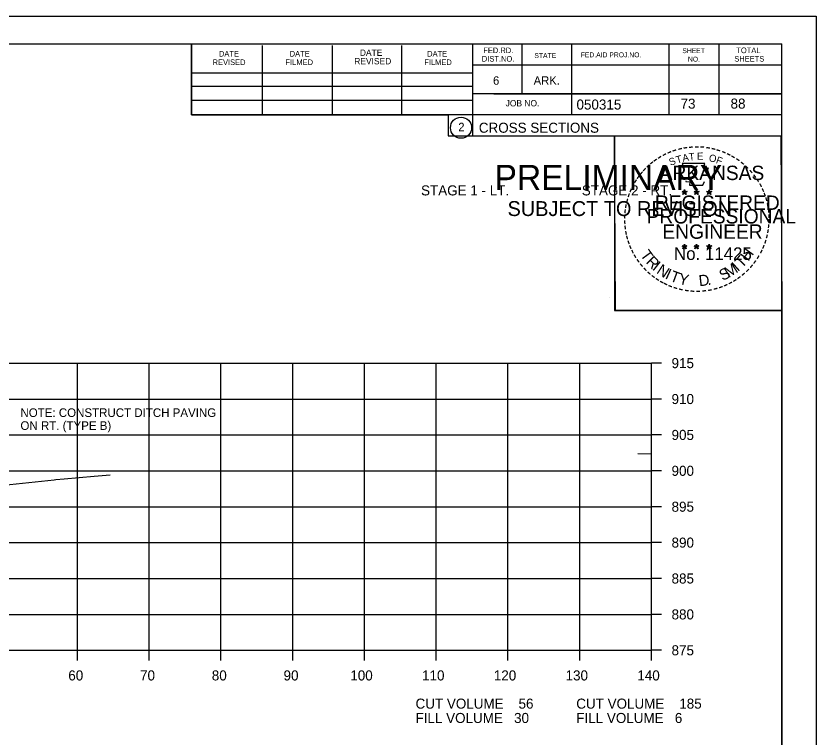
# Model space of a CAD drawing. Extents: x 1486524 to 1499135, y 326561 to 337924.
# Drawn here: x 1489034.3 to 1489145.8, y 333105.4 to 333206 of the extents above; entities that cross this region are included whole.
import ezdxf

# ---------------------------------------------------------------- set-up
doc = ezdxf.new("R2010")
doc.units = 0
for name, color, linetype in [('Default', 7, 'Continuous'), ('E_Const Align', 7, 'Continuous'), ('E_Const Align Station', 7, 'Continuous'), ('E_Ownership Information', 7, 'Continuous'), ('E_Property Line', 7, 'Continuous'), ('E_Quarter Calls', 7, 'Continuous'), ('E_Section Line', 7, 'Continuous'), ('E_Station Offset', 7, 'Continuous'), ('E_Tract Number', 7, 'Continuous'), ('S_SIXTEEN_SECTION', 7, 'Continuous')]:
    doc.layers.add(name, color=color, linetype=linetype)

msp = doc.modelspace()

# ---------------------------------------------------------------- linework, layer by layer
at = {"layer": 'E_Const Align'}
for p, q in [((1489122.89, 333117.63), (1489122.89, 333157.63)), ((1489124.29, 333157.63), (1489122.89, 333157.63)), ((1489124.29, 333152.63), (1489122.89, 333152.63)), ((1489124.29, 333147.63), (1489122.89, 333147.63)), ((1489124.29, 333142.63), (1489122.89, 333142.63)), ((1489124.29, 333137.63), (1489122.89, 333137.63)), ((1489124.29, 333132.63), (1489122.89, 333132.63)), ((1489124.29, 333127.63), (1489122.89, 333127.63)), ((1489124.29, 333122.63), (1489122.89, 333122.63)), ((1488842.89, 333117.63), (1489122.89, 333117.63)), ((1489042.89, 333116.23), (1489042.89, 333117.63)), ((1489052.89, 333116.23), (1489052.89, 333117.63)), ((1489062.89, 333116.23), (1489062.89, 333117.63)), ((1489072.89, 333116.23), (1489072.89, 333117.63)), ((1489082.89, 333116.23), (1489082.89, 333117.63)), ((1489092.89, 333116.23), (1489092.89, 333117.63)), ((1489102.89, 333116.23), (1489102.89, 333117.63)), ((1489112.89, 333116.23), (1489112.89, 333117.63)), ((1489122.89, 333116.23), (1489122.89, 333117.63)), ((1489124.29, 333117.63), (1489122.89, 333117.63))]:
    msp.add_line(p, q, dxfattribs=at)
at = {"layer": 'E_Ownership Information'}
for p, q in [((1488842.89, 333157.63), (1489122.89, 333157.63)), ((1488842.89, 333157.63), (1489122.89, 333157.63)), ((1489042.89, 333117.63), (1489042.89, 333157.63)), ((1489042.89, 333117.63), (1489042.89, 333157.63)), ((1489052.89, 333117.63), (1489052.89, 333157.63)), ((1489052.89, 333117.63), (1489052.89, 333157.63)), ((1489062.89, 333117.63), (1489062.89, 333157.63)), ((1489062.89, 333117.63), (1489062.89, 333157.63)), ((1489072.89, 333117.63), (1489072.89, 333157.63)), ((1489072.89, 333117.63), (1489072.89, 333157.63)), ((1489082.89, 333117.63), (1489082.89, 333157.63)), ((1489082.89, 333117.63), (1489082.89, 333157.63)), ((1489092.89, 333117.63), (1489092.89, 333157.63)), ((1489092.89, 333117.63), (1489092.89, 333157.63)), ((1489102.89, 333117.63), (1489102.89, 333157.63)), ((1489102.89, 333117.63), (1489102.89, 333157.63)), ((1489112.89, 333117.63), (1489112.89, 333157.63)), ((1489112.89, 333117.63), (1489112.89, 333157.63)), ((1489122.89, 333117.63), (1489122.89, 333157.63)), ((1489122.89, 333117.63), (1489122.89, 333157.63)), ((1488842.89, 333152.63), (1489122.89, 333152.63)), ((1488842.89, 333152.63), (1489122.89, 333152.63)), ((1488842.89, 333147.63), (1489122.89, 333147.63)), ((1488842.89, 333147.63), (1489122.89, 333147.63)), ((1488842.89, 333142.63), (1489122.89, 333142.63)), ((1488842.89, 333142.63), (1489122.89, 333142.63)), ((1488842.89, 333137.63), (1489122.89, 333137.63)), ((1488842.89, 333137.63), (1489122.89, 333137.63)), ((1488842.89, 333132.63), (1489122.89, 333132.63)), ((1488842.89, 333132.63), (1489122.89, 333132.63)), ((1488842.89, 333127.63), (1489122.89, 333127.63)), ((1488842.89, 333127.63), (1489122.89, 333127.63)), ((1488842.89, 333122.63), (1489122.89, 333122.63)), ((1488842.89, 333122.63), (1489122.89, 333122.63)), ((1488842.89, 333117.63), (1489122.89, 333117.63)), ((1488842.89, 333117.63), (1489122.89, 333117.63))]:
    msp.add_line(p, q, dxfattribs=at)
at = {"layer": 'E_Property Line'}
for p, q in [((1488824.89, 333202.09), (1489141.07, 333202.09)), ((1489058.81, 333192.21), (1489058.81, 333202.09)), ((1489068.67, 333192.21), (1489068.67, 333201.89)), ((1489078.43, 333192.21), (1489078.43, 333201.89)), ((1489088.11, 333192.21), (1489088.11, 333201.89)), ((1489097.97, 333202.09), (1489097.97, 333189.29)), ((1489104.81, 333202.09), (1489104.81, 333195.15)), ((1489111.75, 333202.09), (1489111.75, 333192.21)), ((1489125.33, 333202.09), (1489125.33, 333192.21)), ((1489132.27, 333202.09), (1489132.27, 333192.21)), ((1489141.07, 332996.63), (1489141.07, 333202.09)), ((1489141.07, 333199.15), (1489097.97, 333199.15)), ((1489141.07, 333199.17), (1489141.07, 333199.17)), ((1489058.81, 333198.07), (1489097.97, 333198.07)), ((1489058.81, 333196.21), (1489097.97, 333196.21)), ((1489141.07, 333195.15), (1489097.97, 333195.15)), ((1489100.93, 333195.15), (1489141.07, 333195.15)), ((1489058.81, 333192.21), (1489058.81, 333194.27)), ((1489058.81, 333194.27), (1489097.97, 333194.27)), ((1489141.07, 333192.21), (1489058.81, 333192.21)), ((1489097.97, 333189.29), (1489141.07, 333189.29))]:
    msp.add_line(p, q, dxfattribs=at)
msp.add_circle((1489096.35, 333190.42), 1.47, dxfattribs=at)
at = {"layer": 'E_Quarter Calls'}
for p, q in [((1488812.48, 333205.98), (1489145.82, 333205.98)), ((1489117.1, 333166.83), (1489117.1, 333166.83))]:
    msp.add_line(p, q, dxfattribs=at)
for points in [[(1488812.48, 333205.98), (1489145.82, 333205.98), (1489145.82, 332992.64), (1488812.48, 332992.64)], [(1489058.81, 333202.09), (1489058.81, 333192.21), (1489094.54, 333192.21), (1489094.54, 333189.29), (1489117.74, 333189.29), (1489117.74, 333164.95), (1489141.07, 333164.95), (1489141.07, 332996.63), (1488824.89, 332996.63), (1488824.89, 333202.09)], [(1489117.74, 333189.29), (1489140.94, 333189.29), (1489141.07, 333164.95), (1489117.86, 333164.95)]]:
    msp.add_lwpolyline(points, close=True, dxfattribs=at)
at = {"layer": 'E_Tract Number'}
for points in [[(1489121.01, 333145.02), (1489122.89, 333145)], [(1489029.01, 333140.26), (1489039.63, 333141.38), (1489039.88, 333141.4), (1489041.05, 333141.5), (1489045.21, 333141.88), (1489047.46, 333142.07)]]:
    msp.add_lwpolyline(points, dxfattribs=at)
at = {"layer": 'S_SIXTEEN_SECTION'}
for p, q in [((1489127.15, 333181.54), (1489127.5, 333181.43)), ((1489127.15, 333181.54), (1489127.4, 333181.5)), ((1489127.15, 333181.54), (1489127.39, 333181.42)), ((1489127.28, 333181.13), (1489127.5, 333181.43)), ((1489127.28, 333181.13), (1489127.41, 333181.38)), ((1489127.28, 333181.13), (1489127.5, 333181.35)), ((1489127.5, 333181.8), (1489127.46, 333181.54)), ((1489127.5, 333181.43), (1489127.5, 333181.8)), ((1489127.5, 333181.8), (1489127.55, 333181.55)), ((1489127.85, 333181.54), (1489127.5, 333181.43)), ((1489127.71, 333181.13), (1489127.5, 333181.43)), ((1489127.71, 333181.13), (1489127.5, 333181.35)), ((1489127.85, 333181.54), (1489127.56, 333181.49)), ((1489127.71, 333181.13), (1489127.58, 333181.43)), ((1489127.85, 333181.54), (1489127.64, 333181.44)), ((1489128.82, 333181.54), (1489129.17, 333181.43)), ((1489128.82, 333181.54), (1489129.07, 333181.5)), ((1489128.82, 333181.54), (1489129.06, 333181.42)), ((1489128.95, 333181.13), (1489129.17, 333181.43)), ((1489128.95, 333181.13), (1489129.08, 333181.38)), ((1489128.95, 333181.13), (1489129.17, 333181.35)), ((1489129.17, 333181.8), (1489129.13, 333181.54)), ((1489129.17, 333181.43), (1489129.17, 333181.8)), ((1489129.17, 333181.8), (1489129.22, 333181.55)), ((1489129.52, 333181.54), (1489129.17, 333181.43)), ((1489129.38, 333181.13), (1489129.17, 333181.43)), ((1489129.38, 333181.13), (1489129.17, 333181.35)), ((1489129.52, 333181.54), (1489129.23, 333181.49)), ((1489129.38, 333181.13), (1489129.25, 333181.43)), ((1489129.52, 333181.54), (1489129.31, 333181.44)), ((1489130.58, 333181.53), (1489130.93, 333181.42)), ((1489130.58, 333181.53), (1489130.84, 333181.49)), ((1489130.58, 333181.53), (1489130.82, 333181.41)), ((1489130.72, 333181.12), (1489130.93, 333181.42)), ((1489130.72, 333181.12), (1489130.84, 333181.37)), ((1489130.72, 333181.12), (1489130.93, 333181.34)), ((1489130.93, 333181.78), (1489130.89, 333181.53)), ((1489130.93, 333181.42), (1489130.93, 333181.78)), ((1489130.93, 333181.78), (1489130.98, 333181.53)), ((1489131.28, 333181.53), (1489130.93, 333181.42)), ((1489131.15, 333181.12), (1489130.93, 333181.42)), ((1489131.15, 333181.12), (1489130.93, 333181.34)), ((1489131.28, 333181.53), (1489130.99, 333181.48)), ((1489131.15, 333181.12), (1489131.01, 333181.41)), ((1489131.28, 333181.53), (1489131.08, 333181.43)), ((1489127.15, 333173.97), (1489127.5, 333173.86)), ((1489127.15, 333173.97), (1489127.4, 333173.92)), ((1489127.15, 333173.97), (1489127.38, 333173.85)), ((1489127.28, 333173.56), (1489127.5, 333173.86)), ((1489127.28, 333173.56), (1489127.41, 333173.81)), ((1489127.28, 333173.56), (1489127.49, 333173.78)), ((1489127.5, 333174.22), (1489127.45, 333173.97)), ((1489127.71, 333173.56), (1489127.49, 333173.78)), ((1489127.5, 333173.86), (1489127.5, 333174.22)), ((1489127.5, 333174.22), (1489127.54, 333173.97)), ((1489127.84, 333173.97), (1489127.5, 333173.86)), ((1489127.71, 333173.56), (1489127.5, 333173.86)), ((1489127.84, 333173.97), (1489127.56, 333173.92)), ((1489127.71, 333173.56), (1489127.57, 333173.85)), ((1489127.84, 333173.97), (1489127.64, 333173.87)), ((1489128.82, 333173.97), (1489129.16, 333173.86)), ((1489128.82, 333173.97), (1489129.07, 333173.92)), ((1489128.82, 333173.97), (1489129.05, 333173.85)), ((1489128.95, 333173.56), (1489129.16, 333173.86)), ((1489128.95, 333173.56), (1489129.07, 333173.81)), ((1489128.95, 333173.56), (1489129.16, 333173.78)), ((1489129.16, 333174.22), (1489129.12, 333173.97)), ((1489129.16, 333173.86), (1489129.16, 333174.22)), ((1489129.16, 333174.22), (1489129.21, 333173.97)), ((1489129.51, 333173.97), (1489129.16, 333173.86)), ((1489129.38, 333173.56), (1489129.16, 333173.86)), ((1489129.38, 333173.56), (1489129.16, 333173.78)), ((1489129.51, 333173.97), (1489129.23, 333173.92)), ((1489129.38, 333173.56), (1489129.24, 333173.85)), ((1489129.51, 333173.97), (1489129.31, 333173.87)), ((1489130.58, 333173.96), (1489130.93, 333173.85)), ((1489130.58, 333173.96), (1489130.84, 333173.91)), ((1489130.58, 333173.96), (1489130.82, 333173.84)), ((1489130.72, 333173.55), (1489130.93, 333173.85)), ((1489130.72, 333173.55), (1489130.84, 333173.8)), ((1489130.72, 333173.55), (1489130.93, 333173.77)), ((1489130.93, 333174.21), (1489130.89, 333173.96)), ((1489130.93, 333173.85), (1489130.93, 333174.21)), ((1489130.93, 333174.21), (1489130.98, 333173.96)), ((1489131.28, 333173.96), (1489130.93, 333173.85)), ((1489131.14, 333173.55), (1489130.93, 333173.85)), ((1489131.14, 333173.55), (1489130.93, 333173.77)), ((1489131.28, 333173.96), (1489130.99, 333173.91)), ((1489131.14, 333173.55), (1489131.01, 333173.84)), ((1489131.28, 333173.96), (1489131.07, 333173.86))]:
    msp.add_line(p, q, dxfattribs=at)
for points in [[(1489127.19, 333185.42), (1489127.46, 333184.59)], [(1489130.7, 333184.5), (1489130.84, 333184.78), (1489130.16, 333184.76), (1489130.31, 333185.42), (1489127.19, 333185.42)], [(1489127.68, 333183), (1489127.68, 333182.91), (1489128.25, 333182.89), (1489128.19, 333182.42), (1489130.06, 333182.42), (1489130.26, 333182.95)], [(1489127.5, 333181.8), (1489127.71, 333181.13), (1489127.15, 333181.54), (1489127.85, 333181.54), (1489127.28, 333181.13), (1489127.5, 333181.8)], [(1489129.17, 333181.8), (1489129.38, 333181.13), (1489128.82, 333181.54), (1489129.52, 333181.54), (1489128.95, 333181.13), (1489129.17, 333181.8)], [(1489130.93, 333181.78), (1489131.15, 333181.12), (1489130.58, 333181.53), (1489131.28, 333181.53), (1489130.72, 333181.12), (1489130.93, 333181.78)], [(1489127.5, 333174.22), (1489127.71, 333173.56), (1489127.15, 333173.97), (1489127.84, 333173.97), (1489127.28, 333173.56), (1489127.5, 333174.22)], [(1489129.16, 333174.22), (1489129.38, 333173.56), (1489128.82, 333173.97), (1489129.51, 333173.97), (1489128.95, 333173.56), (1489129.16, 333174.22)], [(1489130.93, 333174.21), (1489131.14, 333173.55), (1489130.58, 333173.96), (1489131.28, 333173.96), (1489130.72, 333173.55), (1489130.93, 333174.21)]]:
    msp.add_lwpolyline(points, dxfattribs=at)
for centre, radius in [((1489127.5, 333181.43), 0.172), ((1489127.5, 333181.43), 0.145), ((1489127.5, 333181.43), 0.116), ((1489127.5, 333181.43), 0.0991), ((1489127.5, 333181.43), 0.0747), ((1489127.5, 333181.43), 0.0495), ((1489127.5, 333181.43), 0.0296), ((1489129.17, 333181.43), 0.172), ((1489129.17, 333181.43), 0.145), ((1489129.17, 333181.43), 0.116), ((1489129.17, 333181.43), 0.0991), ((1489129.17, 333181.43), 0.0747), ((1489129.17, 333181.43), 0.0495), ((1489129.17, 333181.43), 0.0296), ((1489130.93, 333181.42), 0.172), ((1489130.93, 333181.42), 0.145), ((1489130.93, 333181.42), 0.116), ((1489130.93, 333181.42), 0.0991), ((1489130.93, 333181.42), 0.0747), ((1489130.93, 333181.42), 0.0495), ((1489130.93, 333181.42), 0.0296), ((1489127.49, 333173.86), 0.172), ((1489127.49, 333173.86), 0.145), ((1489127.49, 333173.86), 0.116), ((1489127.49, 333173.86), 0.0991), ((1489127.49, 333173.86), 0.0747), ((1489127.49, 333173.86), 0.0495), ((1489127.49, 333173.86), 0.0296), ((1489129.16, 333173.86), 0.172), ((1489129.16, 333173.86), 0.145), ((1489129.16, 333173.86), 0.116), ((1489129.16, 333173.86), 0.0991), ((1489129.16, 333173.86), 0.0747), ((1489129.16, 333173.86), 0.0495), ((1489129.16, 333173.86), 0.0296), ((1489130.93, 333173.85), 0.172), ((1489130.93, 333173.85), 0.145), ((1489130.93, 333173.85), 0.116), ((1489130.93, 333173.85), 0.0991), ((1489130.93, 333173.85), 0.0747), ((1489130.93, 333173.85), 0.0495), ((1489130.93, 333173.85), 0.0296)]:
    msp.add_circle(centre, radius, dxfattribs=at)

# ---------------------------------------------------------------- texts
at = {"layer": 'Default'}
for s, height, p in [('STAGE 1 - LT.', 1.4, (1489090.78, 333180.99)), ('STAGE 2 - RT.', 1.4, (1489113.18, 333180.99)), ('NOTE: CONSTRUCT DITCH PAVING', 1.2, (1489034.95, 333150.13)), ('ON RT. (TYPE B)', 1.2, (1489034.95, 333148.33))]:
    msp.add_text(s, height=height, dxfattribs=at).set_placement(p)
at = {"layer": 'E_Const Align Station'}
for s, p in [('915', (1489125.69, 333156.93)), ('910', (1489125.69, 333151.93)), ('905', (1489125.69, 333146.93)), ('900', (1489125.69, 333141.93)), ('895', (1489125.69, 333136.93)), ('890', (1489125.69, 333131.93)), ('885', (1489125.69, 333126.93)), ('880', (1489125.69, 333121.93)), ('875', (1489125.69, 333116.93)), ('60', (1489041.62, 333113.43)), ('70', (1489051.62, 333113.43)), ('80', (1489061.62, 333113.43)), ('90', (1489071.62, 333113.43)), ('100', (1489080.92, 333113.43)), ('110', (1489090.92, 333113.43)), ('120', (1489100.92, 333113.43)), ('130', (1489110.92, 333113.43)), ('140', (1489120.92, 333113.43)), ('CUT VOLUME    56', (1489090.01, 333109.5)), ('CUT VOLUME    185', (1489112.41, 333109.5)), ('FILL VOLUME   30', (1489090.01, 333107.5)), ('FILL VOLUME   6', (1489112.41, 333107.5))]:
    msp.add_text(s, height=1.4, dxfattribs=at).set_placement(p)
at = {"layer": 'E_Property Line'}
for s, height, p in [('DATE', 0.879, (1489082.25, 333200.43)), ('FED.RD.', 0.782, (1489099.45, 333200.81)), ('SHEET', 0.684, (1489127.19, 333200.81)), ('TOTAL', 0.782, (1489134.71, 333200.81)), ('DATE', 0.782, (1489062.61, 333200.33)), ('DATE', 0.782, (1489072.47, 333200.33)), ('REVISED', 0.879, (1489081.47, 333199.25)), ('DATE', 0.782, (1489091.63, 333200.33)), ('DIST.NO.', 0.782, (1489099.25, 333199.63)), ('STATE', 0.684, (1489106.57, 333200.13)), ('FED.AID PROJ.NO.', 0.684, (1489113.03, 333200.23)), ('NO.', 0.684, (1489127.97, 333199.63)), ('SHEETS', 0.782, (1489134.43, 333199.63)), ('REVISED', 0.782, (1489061.73, 333199.15)), ('FILMED', 0.782, (1489071.89, 333199.15)), ('FILMED', 0.782, (1489091.23, 333199.15)), ('6', 1.17, (1489100.81, 333196.41)), ('ARK.', 1.172, (1489106.47, 333196.41)), ('JOB NO.', 0.879, (1489102.57, 333193.39)), ('050315', 1.4, (1489112.44, 333192.95)), ('2', 1.17, (1489095.97, 333189.94)), ('CROSS SECTIONS', 1.4, (1489098.83, 333189.72))]:
    msp.add_text(s, height=height, rotation=360, dxfattribs=at).set_placement(p)
at = {"layer": 'E_Section Line'}
for s, height, p in [('PRELIMINARY', 3.5, (1489101.02, 333181.75)), ('DWB', 0.01, (1489101.76, 333183.6)), ('SUBJECT TO REVISION', 2.0751, (1489102.83, 333178.12))]:
    msp.add_text(s, height=height, rotation=360, dxfattribs=at).set_placement(p)
at = {"layer": 'E_Station Offset'}
for s, p in [('73', (1489126.94, 333193.07)), ('88', (1489133.91, 333193.08))]:
    msp.add_text(s, height=1.4, dxfattribs=at).set_placement(p)
at = {"layer": 'S_SIXTEEN_SECTION'}
for s, height, rotation, p in [('-', 1.6, 10.2193, (1489127.37, 333186.95)), ('-', 1.6, 5.8968, (1489128.1, 333187.06)), ('-', 1.6, 0.1862, (1489128.87, 333187.13)), ('-', 1.6, 357.743, (1489129.59, 333187.12)), ('-', 1.6, 352.1617, (1489130.34, 333187.06)), ('-', 1.6, 28.7918, (1489124.67, 333185.96)), ('-', 1.6, 24.3072, (1489125.31, 333186.28)), ('-', 1.6, 19.1761, (1489125.94, 333186.55)), ('-', 1.6, 13.6301, (1489126.69, 333186.79)), ('A', 1, 11.2132, (1489127.29, 333185.68)), ('T', 1, 6.0228, (1489128.14, 333185.85)), ('E', 1, 0.8323, (1489129.24, 333185.96)), ('O', 1, 350.4515, (1489130.84, 333185.75)), ('-', 1.6, 347.2049, (1489131.05, 333186.95)), ('-', 1.6, 342.3362, (1489131.69, 333186.79)), ('-', 1.6, 337.8551, (1489132.42, 333186.57)), ('-', 1.6, 334.1211, (1489133.06, 333186.3)), ('-', 1.6, 38.9507, (1489123.02, 333184.82)), ('-', 1.6, 36.2317, (1489123.5, 333185.2)), ('-', 1.6, 34.0636, (1489124.08, 333185.59)), ('S', 1, 21.594, (1489125.55, 333185.1)), ('T', 1, 16.4036, (1489126.46, 333185.43)), ('F', 1, 340.0707, (1489131.8, 333185.52)), ('-', 1.6, 329.6409, (1489133.63, 333186.02)), ('-', 1.6, 325.8627, (1489134.28, 333185.66)), ('-', 1.6, 320.5297, (1489134.89, 333185.23)), ('-', 1.6, 48.423, (1489122.14, 333183.92)), ('-', 1.6, 42.9622, (1489122.59, 333184.4)), ('ARKANSAS', 2, 360, (1489124.04, 333183.13)), ('-', 1.6, 315.5786, (1489135.49, 333184.74)), ('-', 1.6, 309.8797, (1489136.06, 333184.19)), ('-', 1.6, 54.2325, (1489121.32, 333182.87)), ('-', 1.6, 50.6142, (1489121.74, 333183.44)), ('-', 1.6, 306.6522, (1489136.58, 333183.59)), ('-', 1.4, 303.6753, (1489137.07, 333183.02)), ('-', 1.6, 62.8713, (1489120.69, 333181.73)), ('-', 1.6, 58.0706, (1489121, 333182.34)), ('-', 1.6, 299.6684, (1489137.39, 333182.42)), ('-', 1.6, 72.3945, (1489120.21, 333180.49)), ('-', 1.6, 67.7743, (1489120.43, 333181.12)), ('DWB', 0.01, 360, (1489127.49, 333181.43)), ('DWB', 0.01, 360, (1489129.16, 333181.43)), ('DWB', 0.01, 360, (1489130.92, 333181.42)), ('-', 1.6, 294.6628, (1489137.71, 333181.8)), ('-', 1.6, 290.5728, (1489137.97, 333181.23)), ('-', 1.6, 75.461, (1489120.01, 333179.77)), ('REGISTERED', 2, 360, (1489123.37, 333178.98)), ('-', 1.6, 285.1233, (1489138.2, 333180.65)), ('-', 1.6, 280.5493, (1489138.4, 333179.9)), ('-', 1.6, 85.1863, (1489119.8, 333178.37)), ('-', 1.6, 81.2013, (1489119.88, 333179.06)), ('PROFESSIONAL', 2, 360, (1489122.22, 333177.08)), ('-', 1.6, 276.5962, (1489138.56, 333179.14)), ('-', 1.6, 89.0622, (1489119.78, 333177.67)), ('-', 1.6, 274.3301, (1489138.62, 333178.41)), ('-', 1.6, 94.1959, (1489119.81, 333176.94)), ('-', 1.6, 98.9479, (1489119.89, 333176.28)), ('ENGINEER', 2, 360, (1489124.41, 333174.95)), ('-', 1.6, 263.5172, (1489138.64, 333177.12)), ('-', 1.6, 269.9407, (1489138.66, 333177.78)), ('-', 1.6, 101.7149, (1489120.02, 333175.54)), ('-', 1.6, 255.7626, (1489138.46, 333175.78)), ('-', 1.6, 260.9953, (1489138.57, 333176.46)), ('-', 1.6, 105.4578, (1489120.18, 333174.95)), ('-', 1.6, 109.0874, (1489120.4, 333174.32)), ('-', 1.6, 252.8681, (1489138.28, 333175.06)), ('-', 1.6, 114.0643, (1489120.65, 333173.72)), ('-', 1.6, 115.7289, (1489120.96, 333173.1)), ('T', 1.54, 306.0406, (1489121.25, 333172.7)), ('No. 11425', 1.757, 360, (1489126.03, 333172)), ('DWB', 0.01, 360, (1489127.48, 333173.85)), ('DWB', 0.01, 360, (1489129.15, 333173.85)), ('DWB', 0.01, 360, (1489130.92, 333173.84)), ('H', 1.54, 54.6088, (1489136.38, 333171.73)), ('-', 1.6, 244.6197, (1489137.79, 333173.76)), ('-', 1.6, 247.8887, (1489138.05, 333174.39)), ('-', 1.6, 120.4471, (1489121.31, 333172.52)), ('-', 1.6, 125.8934, (1489121.72, 333171.96)), ('R', 1.54, 314.005, (1489122.02, 333171.65)), ('T', 1.54, 46.6444, (1489135.49, 333170.79)), ('-', 1.6, 239.0712, (1489137.4, 333173.01)), ('-', 1.6, 130.7181, (1489122.18, 333171.41)), ('I', 1.54, 321.9694, (1489122.92, 333170.72)), ('N', 1.54, 326.5002, (1489123.49, 333170.24)), ('M', 1.54, 32.6563, (1489133.64, 333169.46)), ('I', 1.54, 42.1136, (1489134.92, 333170.31)), ('-', 1.6, 231.2538, (1489136.56, 333171.79)), ('-', 1.6, 233.8452, (1489136.99, 333172.36)), ('-', 1.6, 134.2238, (1489122.7, 333170.86)), ('-', 1.6, 138.9338, (1489123.22, 333170.4)), ('-', 1.6, 144.6463, (1489123.78, 333169.99)), ('I', 1.54, 335.3603, (1489124.69, 333169.46)), ('T', 1.54, 339.8912, (1489125.35, 333169.13)), ('Y', 1.54, 347.8556, (1489126.57, 333168.69)), ('D', 1.54, 6.3969, (1489129.56, 333168.33)), ('S', 1.54, 26.9312, (1489132.8, 333169.06)), ('-', 1.6, 221.0851, (1489135.56, 333170.72)), ('-', 1.6, 225.7653, (1489136.09, 333171.23)), ('-', 1.6, 148.0898, (1489124.34, 333169.62)), ('-', 1.6, 151.5704, (1489124.92, 333169.29)), ('-', 1.6, 154.6002, (1489125.44, 333169.05)), ('-', 1.6, 207.3568, (1489133.92, 333169.51)), ('-', 1.6, 212.2491, (1489134.48, 333169.86)), ('-', 1.6, 215.7363, (1489135.01, 333170.25)), ('-', 1.6, 158.5612, (1489126.06, 333168.79)), ('-', 1.6, 162.7983, (1489126.75, 333168.58)), ('-', 1.6, 167.5555, (1489127.46, 333168.42)), ('-', 1.6, 173.1155, (1489128.24, 333168.31)), ('-', 1.6, 176.5183, (1489128.98, 333168.25)), ('-', 1.6, 181.5918, (1489129.73, 333168.27)), ('-', 1.6, 185.8167, (1489130.54, 333168.35)), ('-', 1.6, 191.2858, (1489131.27, 333168.48)), ('.', 1.54, 13.7642, (1489130.75, 333168.46)), ('-', 1.6, 195.4743, (1489132, 333168.68)), ('-', 1.6, 200.7184, (1489132.68, 333168.92)), ('-', 1.6, 204.2516, (1489133.3, 333169.19))]:
    msp.add_text(s, height=height, rotation=rotation, dxfattribs=at).set_placement(p)

doc.saveas('drawing.dxf')
